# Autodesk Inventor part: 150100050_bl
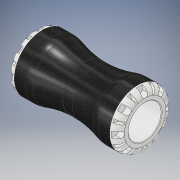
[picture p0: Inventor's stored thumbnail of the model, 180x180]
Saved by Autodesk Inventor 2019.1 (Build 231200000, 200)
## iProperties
Created: 2016-12
Part Number: 150100050_bl
Material: PVC-Piping
Description: PLASSON G-PLASS COUPLING 50X50
Document SubType Name: Modeling
Designer: KIM
Mass: 95.2094 g
Surface Area: 200.83 cm^2
Volume: 68.0067 cm^3
Density: 1.4 g/cm^3
Appearance: White
ILogicFactory: False
Author: KIM
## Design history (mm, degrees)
derived "150100.ipt"
feature "Solid1::150100.ipt" dims "ScaleForDerivedMember" = 10
tag "TaggingFeature1"
body "Solid1"
other parameters: "d2" = 82 [user parameter], "d4" = 4.16667 [user parameter], "d11" = 9 [user parameter], "d13" = 9 [user parameter], "d14" = 0 [user parameter], "d16" = 360 deg [user parameter], "d18" = 8 deg [user parameter], "d19" = 1 [user parameter], "d20" = 8 deg [user parameter], "d21" = 1 [user parameter], "d23" = 0 [user parameter], "d25" = 360 deg [user parameter], "d27" = 34 [user parameter], "d28" = 12.5 [user parameter], "d29" = 15 [user parameter], "d30" = 15 [user parameter], "d31" = 0 [user parameter], "d33" = 0 [user parameter], "d37" = 33.4 [user parameter], "d38" = 0.85 [user parameter], "d43" = 6.25 [user parameter], "d45" = 33.4 [user parameter], "d46" = 68 [user parameter], "d47" = 85 [user parameter], "d48" = 167 [user parameter], "d50" = 360 deg [user parameter], "d54" = 0.513 [user parameter], "E_" = 85 [user parameter], "H_" = 167 [user parameter], "l_" = 82 [user parameter], "d12" = 62.5 [user parameter], "d42" = 85 [user parameter], "d52" = 11.25 [user parameter]
